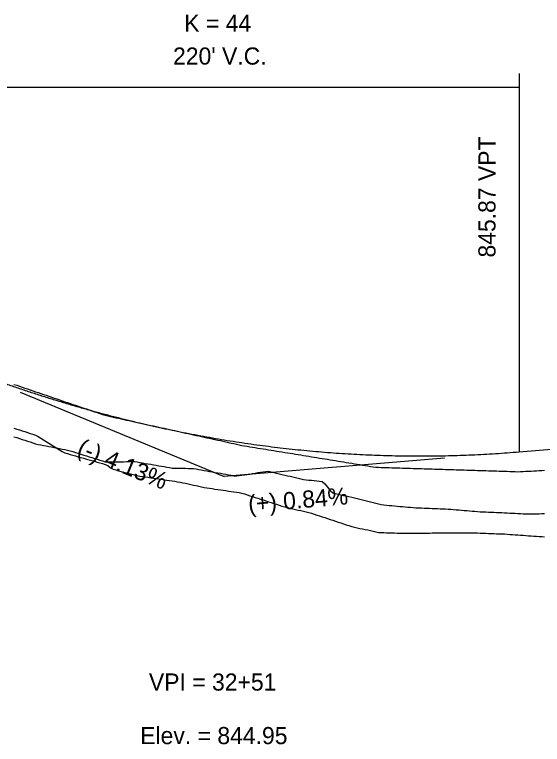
# Model space of a CAD drawing. Extents: x 1733669 to 1739080, y 1214897 to 1219897.
# Drawn here: x 1735052.5 to 1735249.5, y 1217746.2 to 1218018.8 of the extents above; entities that cross this region are included whole.
import ezdxf

# ---------------------------------------------------------------- set-up
doc = ezdxf.new("R2010")
doc.units = 0
for name, color, linetype in [('RD_DDB_GradeTX', 7, 'Continuous'), ('RD_DDB_Profile_EX', 7, 'Continuous'), ('RD_DDB_Profile_Lbl', 7, 'Continuous'), ('RD_DDB_Profile_PR', 7, 'Continuous'), ('RD_DDB_StripGrade', 7, 'Continuous'), ('RD_DDB_VCLbl', 7, 'Continuous'), ('RD_Sketch1', 7, 'Continuous'), ('RD_Sketch2', 7, 'Continuous')]:
    doc.layers.add(name, color=color, linetype=linetype)

msp = doc.modelspace()

# ---------------------------------------------------------------- linework, layer by layer
at = {"layer": 'RD_DDB_GradeTX'}
for p in [(1735054.62, 1217877.75), (1735212.88, 1217853.15)]:
    msp.add_line(p, (1735130.77, 1217846.28), dxfattribs=at)
at = {"layer": 'RD_DDB_Profile_EX'}
for points in [[(1735052.3, 1217880.65), (1735053.3, 1217880.31), (1735054.3, 1217879.97), (1735055.3, 1217879.63), (1735056.3, 1217879.29), (1735057.3, 1217878.95), (1735058.3, 1217878.61), (1735059.3, 1217878.27), (1735060.3, 1217877.93), (1735061.3, 1217877.59), (1735062.3, 1217877.26), (1735063.3, 1217876.92), (1735064.3, 1217876.58), (1735065.3, 1217876.24), (1735066.3, 1217875.9), (1735067.3, 1217875.56), (1735068.3, 1217875.22), (1735069.3, 1217874.88), (1735070.3, 1217874.54), (1735071.3, 1217874.2), (1735072.3, 1217873.86), (1735073.3, 1217873.52), (1735074.3, 1217873.18), (1735075.3, 1217872.84), (1735076.3, 1217872.5), (1735077.3, 1217872.16), (1735078.3, 1217871.82), (1735079.3, 1217871.48), (1735080.3, 1217871.14), (1735081.3, 1217870.8), (1735082.3, 1217870.46), (1735083.3, 1217870.12)], [(1735083.3, 1217870.12), (1735084.3, 1217869.78), (1735085.3, 1217869.44), (1735086.3, 1217869.12), (1735087.3, 1217868.88), (1735088.3, 1217868.66), (1735089.3, 1217868.44), (1735090.3, 1217868.22), (1735091.3, 1217868), (1735092.3, 1217867.78), (1735093.3, 1217867.56), (1735094.3, 1217867.34), (1735095.3, 1217867.12), (1735096.3, 1217866.9), (1735097.3, 1217866.68), (1735098.3, 1217866.46), (1735099.3, 1217866.24), (1735100.3, 1217866.02), (1735101.3, 1217865.8), (1735102.3, 1217865.58), (1735103.3, 1217865.36), (1735104.3, 1217865.14), (1735105.3, 1217864.92), (1735106.3, 1217864.7), (1735107.3, 1217864.48), (1735108.3, 1217864.26), (1735109.3, 1217864.04), (1735110.3, 1217863.82), (1735111.3, 1217863.6), (1735112.3, 1217863.38), (1735113.3, 1217863.16), (1735114.3, 1217862.94), (1735115.3, 1217862.72), (1735116.3, 1217862.5), (1735117.3, 1217862.28), (1735118.3, 1217862.06), (1735119.3, 1217861.84), (1735120.3, 1217861.62), (1735121.3, 1217861.4), (1735122.3, 1217861.18), (1735123.3, 1217860.96), (1735124.3, 1217860.74), (1735125.3, 1217860.52), (1735126.3, 1217860.3), (1735127.3, 1217860.08), (1735128.3, 1217859.86), (1735129.3, 1217859.64), (1735130.3, 1217859.42), (1735131.3, 1217859.2), (1735132.3, 1217858.98), (1735133.3, 1217858.76), (1735134.3, 1217858.54), (1735135.3, 1217858.32), (1735136.3, 1217858.1), (1735137.3, 1217857.88), (1735138.3, 1217857.69), (1735139.3, 1217857.53), (1735140.3, 1217857.37), (1735141.3, 1217857.21), (1735142.3, 1217857.05), (1735143.3, 1217856.89), (1735144.3, 1217856.73), (1735145.3, 1217856.57), (1735146.3, 1217856.41), (1735147.3, 1217856.24), (1735148.3, 1217856.08), (1735149.3, 1217855.92), (1735150.3, 1217855.76), (1735151.3, 1217855.6), (1735152.3, 1217855.44), (1735153.3, 1217855.28), (1735154.3, 1217855.12), (1735155.3, 1217854.96), (1735156.3, 1217854.8), (1735157.3, 1217854.63), (1735158.3, 1217854.47), (1735159.3, 1217854.3), (1735160.3, 1217854.14), (1735161.3, 1217853.97), (1735162.3, 1217853.81), (1735163.3, 1217853.65), (1735164.3, 1217853.48), (1735165.3, 1217853.32), (1735166.3, 1217853.16), (1735167.3, 1217852.99), (1735168.3, 1217852.83), (1735169.3, 1217852.67), (1735170.3, 1217852.5), (1735171.3, 1217852.34), (1735172.3, 1217852.17), (1735173.3, 1217852.01), (1735174.3, 1217851.85), (1735175.3, 1217851.68), (1735176.3, 1217851.52), (1735177.3, 1217851.35), (1735178.3, 1217851.19), (1735179.3, 1217851.03), (1735180.3, 1217850.86), (1735181.3, 1217850.7), (1735182.3, 1217850.53), (1735183.3, 1217850.37)], [(1735183.3, 1217850.37), (1735184.3, 1217850.21), (1735185.3, 1217850.04), (1735186.3, 1217849.88), (1735187.3, 1217849.73), (1735188.3, 1217849.69), (1735189.3, 1217849.66), (1735190.3, 1217849.63), (1735191.3, 1217849.59), (1735192.3, 1217849.56), (1735193.3, 1217849.53), (1735194.3, 1217849.5), (1735195.3, 1217849.47), (1735196.3, 1217849.44), (1735197.3, 1217849.41), (1735198.3, 1217849.38), (1735199.3, 1217849.35), (1735200.3, 1217849.32), (1735201.3, 1217849.29), (1735202.3, 1217849.26), (1735203.3, 1217849.23), (1735204.3, 1217849.2), (1735205.3, 1217849.17), (1735206.3, 1217849.14), (1735207.3, 1217849.11), (1735208.3, 1217849.08), (1735209.3, 1217849.05), (1735210.3, 1217849.02), (1735211.3, 1217848.99), (1735212.3, 1217848.96), (1735213.3, 1217848.93), (1735214.3, 1217848.9), (1735215.3, 1217848.84), (1735216.3, 1217848.81), (1735217.3, 1217848.78), (1735218.3, 1217848.75), (1735219.3, 1217848.72), (1735220.3, 1217848.69), (1735221.3, 1217848.65), (1735222.3, 1217848.62), (1735223.3, 1217848.59), (1735224.3, 1217848.56), (1735225.3, 1217848.53), (1735226.3, 1217848.5), (1735227.3, 1217848.47), (1735228.3, 1217848.44), (1735229.3, 1217848.41), (1735230.3, 1217848.38), (1735231.3, 1217848.35), (1735232.3, 1217848.32), (1735233.3, 1217848.29), (1735234.3, 1217848.26), (1735235.3, 1217848.23), (1735236.3, 1217848.2), (1735237.3, 1217848.17), (1735238.3, 1217848.14), (1735239.3, 1217848.11), (1735240.3, 1217848.05), (1735241.3, 1217848.08), (1735242.3, 1217848.14), (1735243.3, 1217848.19), (1735244.3, 1217848.25), (1735245.3, 1217848.3), (1735246.3, 1217848.36), (1735247.3, 1217848.42), (1735248.3, 1217848.47), (1735249.3, 1217848.53), (1735250.3, 1217848.58)]]:
    msp.add_lwpolyline(points, dxfattribs=at)
at = {"layer": 'RD_DDB_Profile_PR'}
msp.add_line((1735240.77, 1217855.48), (1735271.77, 1217858.07), dxfattribs=at)
msp.add_spline([(1735020.77, 1217891.74), (1735025.17, 1217889.94), (1735029.57, 1217888.19), (1735033.97, 1217886.48), (1735038.37, 1217884.81), (1735042.77, 1217883.19), (1735047.17, 1217881.61), (1735051.57, 1217880.08), (1735055.97, 1217878.59), (1735060.37, 1217877.14), (1735064.77, 1217875.74), (1735069.17, 1217874.38), (1735073.57, 1217873.06), (1735077.97, 1217871.79), (1735082.37, 1217870.56), (1735086.77, 1217869.38), (1735091.17, 1217868.24), (1735095.57, 1217867.14), (1735099.97, 1217866.09), (1735104.37, 1217865.08), (1735108.77, 1217864.11), (1735113.17, 1217863.19), (1735117.57, 1217862.31), (1735121.97, 1217861.48), (1735126.37, 1217860.69), (1735130.77, 1217859.94), (1735135.17, 1217859.24), (1735139.57, 1217858.58), (1735143.97, 1217857.96), (1735148.37, 1217857.39), (1735152.77, 1217856.86), (1735157.17, 1217856.38), (1735161.57, 1217855.94), (1735165.97, 1217855.54), (1735170.37, 1217855.19), (1735174.77, 1217854.88), (1735179.17, 1217854.61), (1735183.57, 1217854.39), (1735187.97, 1217854.21), (1735192.37, 1217854.08), (1735196.77, 1217853.98), (1735201.17, 1217853.94), (1735205.57, 1217853.93), (1735209.97, 1217853.97), (1735214.37, 1217854.06), (1735218.77, 1217854.19), (1735223.17, 1217854.36), (1735227.57, 1217854.57), (1735231.97, 1217854.83), (1735236.37, 1217855.13), (1735240.77, 1217855.48)], degree=3, dxfattribs=at)
at = {"layer": 'RD_DDB_VCLbl'}
for p, q in [((1735240.77, 1217996.74), (1735240.77, 1217855.48)), ((1735020.77, 1217991.74), (1735240.77, 1217991.74))]:
    msp.add_line(p, q, dxfattribs=at)
at = {"layer": 'RD_Sketch1'}
for points in [[(1735052.3, 1217861.11), (1735053.3, 1217860.79), (1735054.3, 1217860.46), (1735055.3, 1217860.13), (1735056.3, 1217859.81), (1735057.3, 1217859.48), (1735058.3, 1217859.16), (1735059.3, 1217858.83), (1735060.3, 1217858.5), (1735061.3, 1217858.25), (1735062.3, 1217858.05), (1735063.3, 1217857.86), (1735064.3, 1217857.67), (1735065.3, 1217857.48), (1735066.3, 1217857.28), (1735067.3, 1217857.09), (1735068.3, 1217856.9), (1735069.3, 1217856.71), (1735070.3, 1217856.51), (1735071.3, 1217856.32), (1735072.3, 1217856.13), (1735073.3, 1217855.85), (1735074.3, 1217855.54), (1735075.3, 1217855.22), (1735076.3, 1217854.91), (1735077.3, 1217854.59), (1735078.3, 1217854.27), (1735079.3, 1217853.96), (1735080.3, 1217853.64), (1735081.3, 1217853.33), (1735082.3, 1217853.01), (1735083.3, 1217852.69)], [(1735083.3, 1217852.69), (1735084.3, 1217852.38), (1735085.3, 1217852.06), (1735086.3, 1217851.75), (1735087.3, 1217851.76), (1735088.3, 1217851.76), (1735089.3, 1217851.77), (1735090.3, 1217851.77), (1735091.3, 1217851.78), (1735092.3, 1217851.79), (1735093.3, 1217851.79), (1735094.3, 1217851.8), (1735095.3, 1217851.8), (1735096.3, 1217851.81), (1735097.3, 1217851.82), (1735098.3, 1217851.69), (1735099.3, 1217851.51), (1735100.3, 1217851.34), (1735101.3, 1217851.16), (1735102.3, 1217850.99), (1735103.3, 1217850.81), (1735104.3, 1217850.64), (1735105.3, 1217850.46), (1735106.3, 1217850.29), (1735107.3, 1217850.11), (1735108.3, 1217849.94), (1735109.3, 1217849.77), (1735110.3, 1217849.59), (1735111.3, 1217849.42), (1735112.3, 1217849.39), (1735113.3, 1217849.37), (1735114.3, 1217849.36), (1735115.3, 1217849.34), (1735116.3, 1217849.32), (1735117.3, 1217849.3), (1735118.3, 1217849.29), (1735119.3, 1217849.27), (1735120.3, 1217849.08), (1735121.3, 1217848.9), (1735122.3, 1217848.72), (1735123.3, 1217848.53), (1735124.3, 1217848.35), (1735125.3, 1217848.17), (1735126.3, 1217847.99), (1735127.3, 1217847.8), (1735128.3, 1217847.62), (1735129.3, 1217847.44), (1735130.3, 1217847.25), (1735131.3, 1217847.07), (1735132.3, 1217846.89), (1735133.3, 1217846.7), (1735134.3, 1217846.52), (1735135.3, 1217846.56), (1735136.3, 1217846.68), (1735137.3, 1217846.8), (1735138.3, 1217846.92), (1735139.3, 1217847.04), (1735140.3, 1217847.16), (1735141.3, 1217847.34), (1735142.3, 1217847.55), (1735143.3, 1217847.76), (1735144.3, 1217847.89), (1735145.3, 1217848.02), (1735146.3, 1217848.15), (1735147.3, 1217848.23), (1735148.3, 1217847.99), (1735149.3, 1217847.75), (1735150.3, 1217847.51), (1735151.3, 1217847.27), (1735152.3, 1217847.03), (1735153.3, 1217846.79), (1735154.3, 1217846.55), (1735155.3, 1217846.32), (1735156.3, 1217846.08), (1735157.3, 1217845.84), (1735158.3, 1217845.6), (1735159.3, 1217845.36), (1735160.3, 1217845.13), (1735161.3, 1217845.03), (1735162.3, 1217844.93), (1735163.3, 1217844.83), (1735164.3, 1217844.72), (1735165.3, 1217844.62), (1735166.3, 1217844.52), (1735167.3, 1217844.42), (1735168.3, 1217843.57), (1735169.3, 1217842.28), (1735170.3, 1217841), (1735171.3, 1217840.14), (1735172.3, 1217839.91), (1735173.3, 1217839.68), (1735174.3, 1217839.44), (1735175.3, 1217839.21), (1735176.3, 1217838.97), (1735177.3, 1217838.74), (1735178.3, 1217838.5), (1735179.3, 1217838.27), (1735180.3, 1217838.03), (1735181.3, 1217837.8), (1735182.3, 1217837.57), (1735183.3, 1217837.33)], [(1735183.3, 1217837.33), (1735184.3, 1217837.08), (1735185.3, 1217836.83), (1735186.3, 1217836.57), (1735187.3, 1217836.32), (1735188.3, 1217836.07), (1735189.3, 1217835.81), (1735190.3, 1217835.66), (1735191.3, 1217835.57), (1735192.3, 1217835.48), (1735193.3, 1217835.39), (1735194.3, 1217835.3), (1735195.3, 1217835.21), (1735196.3, 1217835.11), (1735197.3, 1217835.02), (1735198.3, 1217834.93), (1735199.3, 1217834.84), (1735200.3, 1217834.75), (1735201.3, 1217834.66), (1735202.3, 1217834.59), (1735203.3, 1217834.55), (1735204.3, 1217834.51), (1735205.3, 1217834.47), (1735206.3, 1217834.43), (1735207.3, 1217834.38), (1735208.3, 1217834.34), (1735209.3, 1217834.3), (1735210.3, 1217834.26), (1735211.3, 1217834.22), (1735212.3, 1217834.18), (1735213.3, 1217834.14), (1735214.3, 1217834.1), (1735215.3, 1217834.03), (1735216.3, 1217833.94), (1735217.3, 1217833.86), (1735218.3, 1217833.78), (1735219.3, 1217833.69), (1735220.3, 1217833.61), (1735221.3, 1217833.52), (1735222.3, 1217833.44), (1735223.3, 1217833.35), (1735224.3, 1217833.27), (1735225.3, 1217833.18), (1735226.3, 1217833.1), (1735227.3, 1217833.05), (1735228.3, 1217833.01), (1735229.3, 1217832.97), (1735230.3, 1217832.92), (1735231.3, 1217832.88), (1735232.3, 1217832.83), (1735233.3, 1217832.79), (1735234.3, 1217832.75), (1735235.3, 1217832.7), (1735236.3, 1217832.66), (1735237.3, 1217832.61), (1735238.3, 1217832.57), (1735239.3, 1217832.53), (1735240.3, 1217832.48), (1735241.3, 1217832.4), (1735242.3, 1217832.33), (1735243.3, 1217832.34), (1735244.3, 1217832.35), (1735245.3, 1217832.35), (1735246.3, 1217832.36), (1735247.3, 1217832.37), (1735248.3, 1217832.37), (1735249.3, 1217832.38), (1735250.3, 1217832.39)]]:
    msp.add_lwpolyline(points, dxfattribs=at)
at = {"layer": 'RD_Sketch2'}
for points in [[(1735052.3, 1217864.26), (1735053.3, 1217863.95), (1735054.3, 1217863.63), (1735055.3, 1217863.31), (1735056.3, 1217863), (1735057.3, 1217862.68), (1735058.3, 1217862.37), (1735059.3, 1217862.05), (1735060.3, 1217861.74), (1735061.3, 1217861.25), (1735062.3, 1217860.62), (1735063.3, 1217859.99), (1735064.3, 1217859.36), (1735065.3, 1217858.73), (1735066.3, 1217858.1), (1735067.3, 1217857.47), (1735068.3, 1217856.84), (1735069.3, 1217856.21), (1735070.3, 1217855.59), (1735071.3, 1217855.1), (1735072.3, 1217854.81), (1735073.3, 1217854.52), (1735074.3, 1217854.23), (1735075.3, 1217853.95), (1735076.3, 1217853.66), (1735077.3, 1217853.37), (1735078.3, 1217853.08), (1735079.3, 1217852.79), (1735080.3, 1217852.5), (1735081.3, 1217852.21), (1735082.3, 1217851.92), (1735083.3, 1217851.63)], [(1735083.3, 1217851.63), (1735084.3, 1217851.34), (1735085.3, 1217851.05), (1735086.3, 1217850.76), (1735087.3, 1217850.32), (1735088.3, 1217849.52), (1735089.3, 1217848.94), (1735090.3, 1217848.69), (1735091.3, 1217848.43), (1735092.3, 1217848.18), (1735093.3, 1217847.92), (1735094.3, 1217847.67), (1735095.3, 1217847.41), (1735096.3, 1217847.16), (1735097.3, 1217846.9), (1735098.3, 1217846.65), (1735099.3, 1217846.4), (1735100.3, 1217846.25), (1735101.3, 1217846.1), (1735102.3, 1217845.95), (1735103.3, 1217845.8), (1735104.3, 1217845.65), (1735105.3, 1217845.5), (1735106.3, 1217845.35), (1735107.3, 1217845.2), (1735108.3, 1217845.05), (1735109.3, 1217844.9), (1735110.3, 1217844.75), (1735111.3, 1217844.6), (1735112.3, 1217844.45), (1735113.3, 1217844.3), (1735114.3, 1217844.15), (1735115.3, 1217843.93), (1735116.3, 1217843.71), (1735117.3, 1217843.49), (1735118.3, 1217843.27), (1735119.3, 1217843.05), (1735120.3, 1217842.83), (1735121.3, 1217842.61), (1735122.3, 1217842.39), (1735123.3, 1217842.17), (1735124.3, 1217842.01), (1735125.3, 1217841.86), (1735126.3, 1217841.71), (1735127.3, 1217841.57), (1735128.3, 1217841.42), (1735129.3, 1217841.27), (1735130.3, 1217841.13), (1735131.3, 1217840.98), (1735132.3, 1217840.83), (1735133.3, 1217840.69), (1735134.3, 1217840.54), (1735135.3, 1217840.39), (1735136.3, 1217840.25), (1735137.3, 1217840.06), (1735138.3, 1217839.74), (1735139.3, 1217839.42), (1735140.3, 1217839.09), (1735141.3, 1217838.77), (1735142.3, 1217838.45), (1735143.3, 1217838.12), (1735144.3, 1217837.8), (1735145.3, 1217837.48), (1735146.3, 1217837.15), (1735147.3, 1217836.83), (1735148.3, 1217836.5), (1735149.3, 1217836.18), (1735150.3, 1217835.86), (1735151.3, 1217835.53), (1735152.3, 1217835.21), (1735153.3, 1217834.89), (1735154.3, 1217834.57), (1735155.3, 1217834.36), (1735156.3, 1217834.15), (1735157.3, 1217833.94), (1735158.3, 1217833.73), (1735159.3, 1217833.52), (1735160.3, 1217833.3), (1735161.3, 1217833.09), (1735162.3, 1217832.84), (1735163.3, 1217832.52), (1735164.3, 1217832.19), (1735165.3, 1217831.86), (1735166.3, 1217831.53), (1735167.3, 1217831.21), (1735168.3, 1217830.88), (1735169.3, 1217830.55), (1735170.3, 1217830.22), (1735171.3, 1217829.89), (1735172.3, 1217829.57), (1735173.3, 1217829.24), (1735174.3, 1217828.91), (1735175.3, 1217828.58), (1735176.3, 1217828.26), (1735177.3, 1217827.93), (1735178.3, 1217827.6), (1735179.3, 1217827.29), (1735180.3, 1217827.09), (1735181.3, 1217826.89), (1735182.3, 1217826.69), (1735183.3, 1217826.49)], [(1735183.3, 1217826.49), (1735184.3, 1217826.29), (1735185.3, 1217826.08), (1735186.3, 1217825.88), (1735187.3, 1217825.64), (1735188.3, 1217825.38), (1735189.3, 1217825.34), (1735190.3, 1217825.31), (1735191.3, 1217825.27), (1735192.3, 1217825.23), (1735193.3, 1217825.19), (1735194.3, 1217825.16), (1735195.3, 1217825.12), (1735196.3, 1217825.08), (1735197.3, 1217825.06), (1735198.3, 1217825.07), (1735199.3, 1217825.08), (1735200.3, 1217825.08), (1735201.3, 1217825.09), (1735202.3, 1217825.1), (1735203.3, 1217825.11), (1735204.3, 1217825.12), (1735205.3, 1217825.13), (1735206.3, 1217825.13), (1735207.3, 1217825.14), (1735208.3, 1217825.15), (1735209.3, 1217825.16), (1735210.3, 1217825.17), (1735211.3, 1217825.17), (1735212.3, 1217825.18), (1735213.3, 1217825.19), (1735214.3, 1217825.2), (1735215.3, 1217825.21), (1735216.3, 1217825.22), (1735217.3, 1217825.22), (1735218.3, 1217825.23), (1735219.3, 1217825.24), (1735220.3, 1217825.25), (1735221.3, 1217825.26), (1735222.3, 1217825.27), (1735223.3, 1217825.24), (1735224.3, 1217825.2), (1735225.3, 1217825.16), (1735226.3, 1217825.13), (1735227.3, 1217825.09), (1735228.3, 1217825.05), (1735229.3, 1217825.01), (1735230.3, 1217824.97), (1735231.3, 1217824.94), (1735232.3, 1217824.9), (1735233.3, 1217824.86), (1735234.3, 1217824.82), (1735235.3, 1217824.78), (1735236.3, 1217824.71), (1735237.3, 1217824.64), (1735238.3, 1217824.57), (1735239.3, 1217824.5), (1735240.3, 1217824.43), (1735241.3, 1217824.36), (1735242.3, 1217824.29), (1735243.3, 1217824.22), (1735244.3, 1217824.15), (1735245.3, 1217824.08), (1735246.3, 1217824.01), (1735247.3, 1217823.94), (1735248.3, 1217823.87), (1735249.3, 1217823.8), (1735250.3, 1217823.73)]]:
    msp.add_lwpolyline(points, dxfattribs=at)

# ---------------------------------------------------------------- texts
at = {"layer": 'RD_DDB_GradeTX'}
for s, rotation, p in [('(-) 4.13%', 337.5464, (1735075.43, 1217854.66)), ('(+) 0.84%', 4.7825, (1735139.96, 1217832.79))]:
    msp.add_text(s, height=6.4, rotation=rotation, dxfattribs=at).set_placement(p)
at = {"layer": 'RD_DDB_Profile_Lbl'}
for s, p in [('VPI = 32+51', (1735102.64, 1217766.28)), ('Elev. = 844.95', (1735099.4, 1217746.28))]:
    msp.add_text(s, height=6.4, dxfattribs=at).set_placement(p)
at = {"layer": 'RD_DDB_StripGrade'}
msp.add_text('845.87 VPT', height=6.4, rotation=90, dxfattribs=at).set_placement((1735231.97, 1217928.05))
at = {"layer": 'RD_DDB_VCLbl'}
for s, p in [('K = 44', (1735115.84, 1218012.38)), ("220' V.C.", (1735111.64, 1218000.1))]:
    msp.add_text(s, height=6.4, dxfattribs=at).set_placement(p)

doc.saveas('drawing.dxf')
